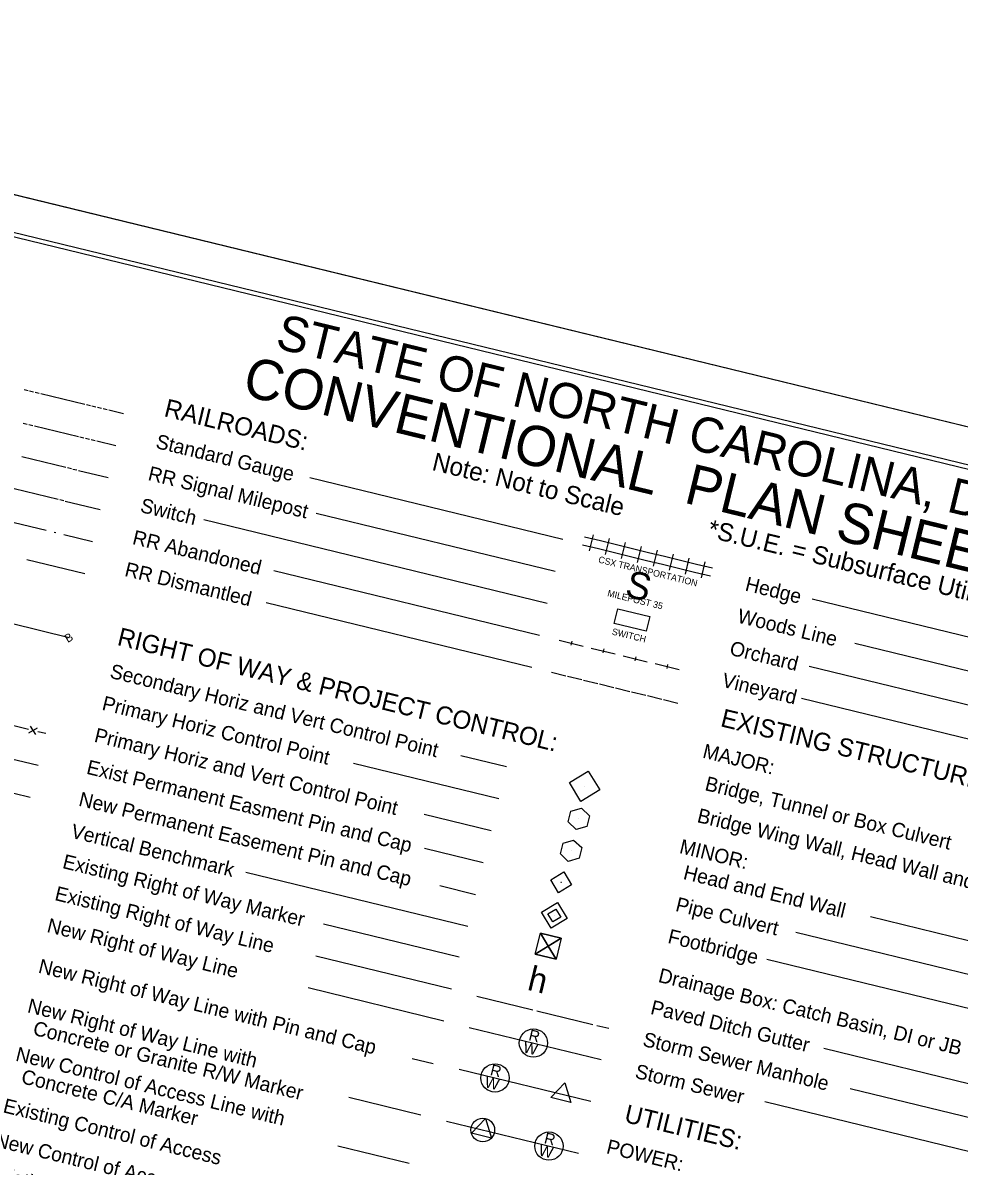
# Model space of a CAD drawing. Extents: x 1532568 to 1534465, y 472683 to 474150.
# Drawn here: x 1533263 to 1533832, y 473455 to 474150 of the extents above; entities that cross this region are included whole.
import ezdxf

# ---------------------------------------------------------------- set-up
doc = ezdxf.new("R2010")
doc.units = 0
for name, color, linetype in [('Prop DSN Text', 7, 'Continuous'), ('Prop ROW Permanent Easement CELL', 7, 'Continuous'), ('Sheet Cutting Line CELL', 7, 'Continuous'), ('Sheet Plot Border Inside CELL', 7, 'Continuous'), ('Sheet Plot Border Outside CELL', 7, 'Continuous'), ('Sheet Symbology CELL', 7, 'Continuous')]:
    doc.layers.add(name, color=color, linetype=linetype)

msp = doc.modelspace()

# ---------------------------------------------------------------- linework, layer by layer
at = {"layer": 'Prop DSN Text'}
for p, q in [((1533604.52, 473685.99), (1533604.52, 473685.99)), ((1533601.06, 473666.24), (1533601.06, 473666.24)), ((1533596.33, 473646.81), (1533596.33, 473646.81)), ((1533590.35, 473627.64), (1533590.35, 473627.64)), ((1533582.47, 473588.83), (1533582.47, 473588.83))]:
    msp.add_line(p, q, dxfattribs=at)
for points in [[(1533595.39, 473688.24), (1533606.81, 473695.2), (1533613.78, 473683.75), (1533602.35, 473676.8)], [(1533591.46, 473651.47), (1533597.93, 473653.26), (1533602.87, 473648.74), (1533601.19, 473642.23), (1533594.69, 473640.3), (1533589.85, 473644.85)], [(1533584.04, 473629.18), (1533591.89, 473633.95), (1533596.66, 473626.1), (1533588.82, 473621.33)], [(1533577.69, 473596.66), (1533590.29, 473593.59), (1533587.23, 473580.99), (1533574.62, 473584.05)]]:
    msp.add_lwpolyline(points, close=True, dxfattribs=at)
for points in [[(1533599.49, 473659.78), (1533594.63, 473664.35), (1533596.21, 473670.81), (1533602.63, 473672.71), (1533607.49, 473668.14), (1533605.9, 473661.61), (1533599.49, 473659.78)], [(1533590.29, 473593.59), (1533574.62, 473584.05), (1533582.46, 473588.82), (1533587.23, 473580.99), (1533577.69, 473596.66)], [(1533582.46, 473588.82), (1533590.29, 473593.59), (1533577.69, 473596.66), (1533582.46, 473588.82)], [(1533582.46, 473588.82), (1533574.62, 473584.05), (1533587.23, 473580.99), (1533582.46, 473588.82)]]:
    msp.add_lwpolyline(points, dxfattribs=at)
msp.add_circle((1533590.35, 473627.64), 0.126, dxfattribs=at)
at = {"layer": 'Prop ROW Permanent Easement CELL'}
msp.add_line((1533586.23, 473607.5), (1533586.23, 473607.5), dxfattribs=at)
for points in [[(1533588.14, 473615.32), (1533594.06, 473605.59), (1533584.33, 473599.67), (1533578.41, 473609.4)], [(1533587.19, 473611.41), (1533590.14, 473606.54), (1533585.28, 473603.58), (1533582.32, 473608.45)]]:
    msp.add_lwpolyline(points, close=True, dxfattribs=at)
at = {"layer": 'Sheet Cutting Line CELL'}
msp.add_line((1534464.62, 473751.79), (1532828.39, 474150.06), dxfattribs=at)
at = {"layer": 'Sheet Plot Border Inside CELL'}
msp.add_lwpolyline([(1532586.18, 473100), (1534205.41, 472705.88), (1534454.94, 473731.04), (1532835.71, 474125.17)], close=True, dxfattribs=at)
at = {"layer": 'Sheet Plot Border Outside CELL'}
msp.add_lwpolyline([(1532568.24, 473081.26), (1534204.47, 472683), (1534464.62, 473751.79), (1532828.39, 474150.06)], close=True, dxfattribs=at)
at = {"layer": 'Sheet Symbology CELL'}
for p, q in [((1533263.74, 473927.27), (1533266.17, 473926.68)), ((1533267.14, 473926.45), (1533269.57, 473925.86)), ((1533270.54, 473925.62), (1533272.97, 473925.03)), ((1533273.94, 473924.79), (1533300.66, 473918.29)), ((1533301.63, 473918.05), (1533304.06, 473917.46)), ((1533305.03, 473917.22), (1533307.46, 473916.63)), ((1533308.43, 473916.4), (1533310.86, 473915.8)), ((1533311.83, 473915.57), (1533314.26, 473914.98)), ((1533315.24, 473914.74), (1533324.27, 473912.54)), ((1533263.27, 473906.8), (1533265.7, 473906.21)), ((1533266.67, 473905.98), (1533269.1, 473905.39)), ((1533270.07, 473905.15), (1533296.79, 473898.65)), ((1533297.76, 473898.41), (1533300.19, 473897.82)), ((1533301.17, 473897.58), (1533303.59, 473896.99)), ((1533304.57, 473896.75), (1533307, 473896.16)), ((1533307.97, 473895.93), (1533319.54, 473893.11)), ((1533262.39, 473886.43), (1533289.11, 473879.93)), ((1533290.08, 473879.69), (1533292.51, 473879.1)), ((1533293.48, 473878.87), (1533295.91, 473878.28)), ((1533296.89, 473878.04), (1533314.81, 473873.68)), ((1533591.36, 473835.97), (1533437.44, 473873.44)), ((1533257.75, 473866.98), (1533284.47, 473860.48)), ((1533285.44, 473860.24), (1533287.87, 473859.65)), ((1533288.84, 473859.41), (1533310.08, 473854.24)), ((1533586.63, 473816.54), (1533441.32, 473851.91)), ((1533257.74, 473846.4), (1533277.17, 473841.67)), ((1533581.9, 473797.11), (1533373.08, 473847.93)), ((1533282.03, 473840.49), (1533283, 473840.25)), ((1533287.86, 473839.07), (1533305.35, 473834.81)), ((1533604.53, 473837.67), (1533614.24, 473835.31)), ((1533607.61, 473829.2), (1533609.98, 473838.92)), ((1533617.33, 473826.84), (1533619.69, 473836.55)), ((1533603.34, 473832.81), (1533613.06, 473830.45)), ((1533613.06, 473830.45), (1533622.78, 473828.08)), ((1533614.24, 473835.31), (1533623.96, 473832.94)), ((1533623.96, 473832.94), (1533633.68, 473830.58)), ((1533627.04, 473824.47), (1533629.41, 473834.19)), ((1533633.68, 473830.58), (1533643.39, 473828.21)), ((1533636.76, 473822.11), (1533639.12, 473831.82)), ((1533646.48, 473819.74), (1533648.84, 473829.46)), ((1533265.4, 473823.95), (1533300.62, 473815.38)), ((1533622.78, 473828.08), (1533632.49, 473825.72)), ((1533632.49, 473825.72), (1533642.21, 473823.35)), ((1533642.21, 473823.35), (1533651.93, 473820.99)), ((1533643.39, 473828.21), (1533653.11, 473825.85)), ((1533653.11, 473825.85), (1533662.82, 473823.48)), ((1533656.19, 473817.38), (1533658.56, 473827.09)), ((1533662.82, 473823.48), (1533672.54, 473821.12)), ((1533665.91, 473815.01), (1533668.27, 473824.73)), ((1533577.17, 473777.68), (1533415.72, 473816.97)), ((1533651.93, 473820.99), (1533661.64, 473818.62)), ((1533661.64, 473818.62), (1533671.36, 473816.26)), ((1533671.36, 473816.26), (1533681.07, 473813.89)), ((1533672.54, 473821.12), (1533682.26, 473818.75)), ((1533675.62, 473812.65), (1533677.99, 473822.36)), ((1533572.44, 473758.24), (1533410.99, 473797.54)), ((1533572.44, 473758.24), (1533410.99, 473797.54)), ((1533949.71, 473749.35), (1533743.06, 473799.65)), ((1533255.94, 473785.09), (1533291.16, 473776.51)), ((1533589.21, 473774.74), (1533603.78, 473771.2)), ((1533596.79, 473774.19), (1533596.2, 473771.76)), ((1533608.64, 473770.01), (1533623.22, 473766.47)), ((1533616.23, 473769.46), (1533615.63, 473767.03)), ((1533944.98, 473729.92), (1533769, 473772.75)), ((1533628.08, 473765.28), (1533642.65, 473761.74)), ((1533635.66, 473764.73), (1533635.07, 473762.3)), ((1533647.51, 473760.55), (1533662.08, 473757.01)), ((1533655.09, 473760), (1533654.5, 473757.57)), ((1533584.48, 473755.31), (1533593.22, 473753.18)), ((1533594.2, 473752.95), (1533602.94, 473750.82)), ((1533940.27, 473710.34), (1533741.14, 473758.81)), ((1533603.91, 473750.58), (1533612.66, 473748.45)), ((1533613.63, 473748.22), (1533622.37, 473746.09)), ((1533623.35, 473745.85), (1533632.09, 473743.72)), ((1533633.06, 473743.49), (1533641.81, 473741.36)), ((1533642.78, 473741.12), (1533651.52, 473738.99)), ((1533935.54, 473690.91), (1533736.41, 473739.38)), ((1533652.49, 473738.76), (1533661.24, 473736.63)), ((1533254.24, 473723.75), (1533266.38, 473720.79)), ((1533266.76, 473718.54), (1533271.83, 473721.63)), ((1533270.84, 473717.55), (1533267.75, 473722.62)), ((1533272.21, 473719.37), (1533276.97, 473718.21)), ((1533194.51, 473717.7), (1533272.24, 473698.78)), ((1533194.51, 473717.7), (1533272.24, 473698.78)), ((1533557.18, 473697.85), (1533529.43, 473704.61)), ((1533189.78, 473698.27), (1533267.51, 473679.35)), ((1533189.78, 473698.27), (1533267.51, 473679.35)), ((1533552.45, 473678.42), (1533464, 473699.95)), ((1533547.72, 473658.99), (1533506.99, 473668.9)), ((1533542.99, 473639.56), (1533507.32, 473648.24)), ((1533533.53, 473600.69), (1533398.62, 473633.53)), ((1533538.26, 473620.12), (1533516.53, 473625.41)), ((1533528.41, 473582.19), (1533445.89, 473602.28)), ((1533903.18, 473576.23), (1533778.52, 473606.57)), ((1533898.45, 473556.8), (1533733.09, 473597.05)), ((1533523.68, 473562.76), (1533441.16, 473582.84)), ((1533893.72, 473537.37), (1533715.45, 473580.76)), ((1533518.95, 473543.32), (1533436.43, 473563.41)), ((1533539.12, 473558.41), (1533573.13, 473550.13)), ((1533575.56, 473549.54), (1533609.57, 473541.26)), ((1533534.5, 473539.41), (1533614.66, 473519.9)), ((1533612, 473540.67), (1533619.28, 473538.89)), ((1533883.21, 473494.2), (1533750.15, 473526.59)), ((1533512.6, 473517.23), (1533499.74, 473520.37)), ((1533528.32, 473514.03), (1533608.48, 473494.52)), ((1533505.03, 473486.11), (1533461.32, 473496.75)), ((1533590.94, 473498.78), (1533590.94, 473498.78)), ((1533878.48, 473474.76), (1533766.09, 473502.12)), ((1533873.75, 473455.33), (1533714.21, 473494.16)), ((1533520.64, 473482.45), (1533600.8, 473462.94)), ((1533542.69, 473477.08), (1533542.69, 473477.08)), ((1533497.87, 473456.72), (1533454.52, 473467.27))]:
    msp.add_line(p, q, dxfattribs=at)
for points in [[(1534442.19, 473731.52), (1532984.74, 474086.27), (1532736.66, 473067.05), (1534194.1, 472712.3)], [(1533624.74, 473793.85), (1533644.17, 473789.12), (1533642.02, 473780.28), (1533622.58, 473785.01)], [(1533584.02, 473496.76), (1533592.65, 473505.78), (1533596.16, 473493.81)], [(1533535.77, 473475.06), (1533544.39, 473484.08), (1533547.91, 473472.1)]]:
    msp.add_lwpolyline(points, close=True, dxfattribs=at)
for centre, radius in [((1533573.48, 473529.92), 8.61), ((1533550.11, 473508.72), 8.61), ((1533542.69, 473477.08), 7.2), ((1533582.91, 473467.29), 8.61)]:
    msp.add_circle(centre, radius, dxfattribs=at)

# ---------------------------------------------------------------- texts
for s, height, rotation, p in [('STATE OF NORTH CAROLINA, DIVISION OF HIGHWAYS', 21.419, 346.31998, (1533415.91, 473952.55)), ('CONVENTIONAL  PLAN SHEET SYMBOLS', 24.4803, 346.31998, (1533395.62, 473923.96)), ('RAILROADS:', 11, 346.31998, (1533348.33, 473911.03)), ('Standard Gauge', 8.75, 346.31998, (1533343.34, 473891.69)), ('Note: Not to Scale', 11, 346.31998, (1533511.25, 473878.36)), ('RR Signal Milepost', 8.75, 346.31998, (1533338.61, 473872.25)), ('Switch', 8.75, 346.31998, (1533333.88, 473852.82)), ('*S.U.E. = Subsurface Utility Engineering', 11, 346.31998, (1533678.83, 473837.57)), ('RR Abandoned', 8.75, 346.31998, (1533329.15, 473833.39)), ('CSX TRANSPORTATION', 4, 346.31998, (1533612.63, 473822.07)), ('RR Dismantled', 8.75, 346.31998, (1533324.42, 473813.96)), ('S', 16.5, 346.31998, (1533628.44, 473801.6)), ('Hedge', 8.75, 346.31998, (1533701.69, 473805.06)), ('MILEPOST 35', 4, 346.31998, (1533618.14, 473801.62)), ('Woods Line', 8.75, 346.31998, (1533696.96, 473785.63)), ('RIGHT OF WAY & PROJECT CONTROL:', 11, 346.31998, (1533319.85, 473771.98)), ('SWITCH', 4, 346.31998, (1533620.9, 473778.3)), ('B', 5, 31.32008, (1533290.33, 473773.08)), ('Orchard', 8.75, 346.31998, (1533692.24, 473766.05)), ('Secondary Horiz and Vert Control Point', 8.75, 346.31998, (1533315.38, 473752.03)), ('Vineyard', 8.75, 346.31998, (1533687.51, 473746.62)), ('Primary Horiz Control Point', 8.75, 346.31998, (1533310.65, 473732.59)), ('EXISTING STRUCTURES:', 11, 346.31998, (1533686.7, 473722.6)), ('Primary Horiz and Vert Control Point', 8.75, 346.31998, (1533305.92, 473713.16)), ('MAJOR:', 8.75, 346.31998, (1533675.85, 473703.51)), ('Exist Permanent Easment Pin and Cap', 8.75, 346.31998, (1533301.19, 473693.73)), ('Bridge, Tunnel or Box Culvert', 8.75, 346.31998, (1533677.24, 473683.74)), ('New Permanent Easement Pin and Cap', 8.75, 346.31998, (1533296.46, 473674.3)), ('Bridge Wing Wall, Head Wall and End Wall', 8.75, 346.31998, (1533672.51, 473664.31)), ('Vertical Benchmark', 8.75, 346.31998, (1533291.73, 473654.86)), ('MINOR:', 8.75, 346.31998, (1533661.73, 473645.51)), ('Existing Right of Way Marker', 8.75, 346.31998, (1533286.62, 473636.36)), ('Head and End Wall', 8.75, 346.31998, (1533664.09, 473629.74)), ('Existing Right of Way Line', 8.75, 346.31998, (1533281.89, 473616.93)), ('Pipe Culvert', 8.75, 346.31998, (1533659.37, 473610.32)), ('New Right of Way Line', 8.75, 346.31998, (1533277.16, 473597.49)), ('Footbridge', 8.75, 346.31998, (1533654.65, 473590.89)), ('New Right of Way Line with Pin and Cap', 8.75, 346.31998, (1533271.93, 473572.8)), ('h', 15, 346.31998, (1533569.11, 473562.43)), ('Drainage Box: Catch Basin, DI or JB', 8.75, 346.31998, (1533648.87, 473567.15)), ('New Right of Way Line with', 8.75, 346.31998, (1533265.28, 473548.69)), ('Paved Ditch Gutter', 8.75, 346.31998, (1533644.14, 473547.71)), ('  Concrete or Granite R/W Marker', 8.75, 346.31998, (1533262.32, 473536.55)), ('R', 6.75, 346.31998, (1533570.12, 473531.78)), ('W', 6.75, 346.31998, (1533566.75, 473524.42)), ('Storm Sewer Manhole', 8.75, 346.31998, (1533639.41, 473528.27)), ('New Control of Access Line with', 8.75, 346.31998, (1533258.13, 473519.31)), ('R', 6.75, 346.31998, (1533546.74, 473510.58)), ('Storm Sewer', 8.75, 346.31998, (1533634.68, 473508.84)), ('  Concrete C/A Marker', 8.75, 346.31998, (1533255.17, 473507.16)), ('W', 6.75, 346.31998, (1533543.37, 473503.22)), ('Existing Control of Access', 8.75, 346.31998, (1533250.48, 473487.91)), ('UTILITIES:', 11, 346.31998, (1533628.14, 473482.04)), ('New Control of Access', 8.75, 346.31998, (1533245.43, 473467.16)), ('R', 6.75, 346.31998, (1533579.55, 473469.15)), ('W', 6.75, 346.31998, (1533576.18, 473461.79)), ('POWER:', 8.75, 346.31998, (1533617.32, 473463.07)), ('Existing Easement Line', 8.75, 346.31998, (1533240.7, 473447.73))]:
    msp.add_text(s, height=height, rotation=rotation, dxfattribs=at).set_placement(p)

doc.saveas('drawing.dxf')
